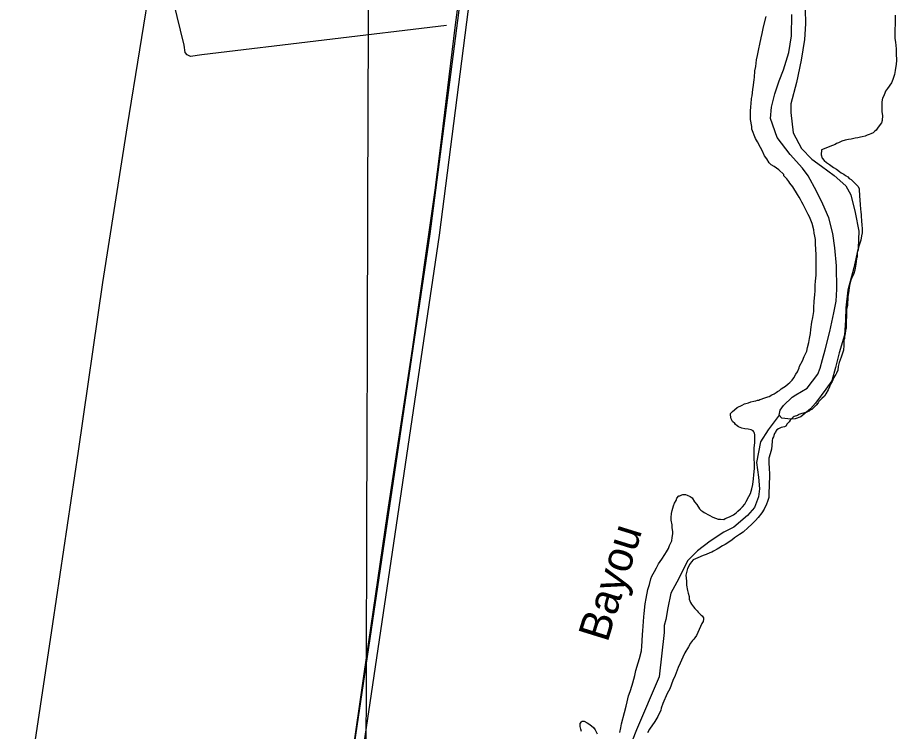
# Model space of a CAD drawing. Extents: x 3161514 to 3199414, y 831166 to 856601.
# Drawn here: x 3169840 to 3172664, y 844859 to 847153 of the extents above; entities that cross this region are included whole.
import ezdxf

# ---------------------------------------------------------------- set-up
doc = ezdxf.new("R2010")
doc.units = 0
for name, color, linetype in [('V-GRID-MAJR', 7, 'Continuous'), ('V-RIVR-IDEN', 7, 'Continuous'), ('V-ROAD-CNTR', 7, 'Continuous'), ('V-SITE-VEGE', 7, 'Continuous'), ('V-TOPO-SHOR', 7, 'Continuous')]:
    doc.layers.add(name, color=color, linetype=linetype)

msp = doc.modelspace()

# ---------------------------------------------------------------- linework, layer by layer
at = {"layer": 'V-GRID-MAJR'}
msp.add_spline([(3170936, 836618.4), (3170954.6, 842678.9), (3170973.1, 848741.2), (3170991.6, 854803.7), (3170991.6, 854805.6)], degree=3, dxfattribs=at)
at = {"layer": 'V-ROAD-CNTR'}
for points in [[(3170729.2, 843056.9), (3170814.5, 843707.1), (3170943.9, 844755.7), (3171195.8, 846454.1), (3171299.1, 847255.9), (3171351.4, 847638.1), (3171399.9, 848031.4), (3171421.5, 848196.3), (3171427.4, 848252.3), (3171427.3, 848291.4), (3171417.9, 848330.6)], [(3170699.4, 843060.8), (3170784.7, 843710.9), (3170914.1, 844759.7), (3171166.1, 846458.2), (3171269.4, 847259.8), (3171321.6, 847642), (3171370.2, 848035.1), (3171391.7, 848199.8), (3171397.4, 848253.8), (3171397.3, 848287.9), (3171388.7, 848323.6)]]:
    msp.add_lwpolyline(points, dxfattribs=at)
at = {"layer": 'V-SITE-VEGE'}
for points in [[(3172367, 846063.4), (3172375.8, 846081.2), (3172378.5, 846092.2), (3172382.1, 846108.3), (3172384.8, 846121.1), (3172387.6, 846137.2), (3172388.6, 846150), (3172392.4, 846173.8), (3172395.2, 846189.1), (3172398, 846208.7), (3172399, 846219.7), (3172399.3, 846241.9), (3172401.3, 846261.5), (3172402.3, 846275.1), (3172402.6, 846293), (3172403.6, 846305.7), (3172405.6, 846325.3), (3172406.5, 846392.6), (3172405, 846406.3), (3172404.4, 846426.7), (3172403.7, 846439.5), (3172401.3, 846450.6), (3172399.7, 846460), (3172398.2, 846470.3), (3172393.3, 846490.8), (3172385.1, 846512.2), (3172380.1, 846519.9), (3172364.4, 846552.5), (3172360.2, 846559.4), (3172356.1, 846568), (3172351.9, 846575.7), (3172346.1, 846584.3), (3172331.1, 846608.4), (3172321.9, 846620.4), (3172317.7, 846625.6), (3172311.8, 846634.2), (3172301.7, 846644.6), (3172301.8, 846648.8), (3172285.8, 846663.5), (3172270.6, 846674), (3172261.3, 846680.1), (3172254.6, 846686.1), (3172247.1, 846699), (3172240.4, 846708.5), (3172233, 846725.6), (3172227.1, 846735.1), (3172217.2, 846753.1), (3172211.4, 846764.3), (3172206.4, 846775.4), (3172203.1, 846784), (3172199.8, 846794.2), (3172199.1, 846802.8), (3172195.2, 846825.8), (3172194.5, 846840.3), (3172194.7, 846851.4), (3172195.7, 846866.7), (3172197.6, 846876.1), (3172198.6, 846892.3), (3172200.5, 846901.6), (3172202.5, 846922), (3172204.3, 846935.6), (3172207.1, 846953.5), (3172208.1, 846960.3), (3172209.2, 846981.6), (3172212, 846995.2), (3172214.8, 847017.3), (3172217.6, 847030.9), (3172221.3, 847052.1), (3172224.9, 847067.4), (3172229.5, 847087.8), (3172232.2, 847101.4), (3172236.8, 847122.7), (3172245.7, 847156.6)], [(3172659.9, 847160.3), (3172658.9, 847085.3), (3172660.4, 847073.4), (3172662.7, 847052), (3172663.3, 847037.5), (3172663.9, 847015.4), (3172662.9, 847003.4), (3172660, 846983), (3172657.3, 846970.3), (3172652.8, 846954.2), (3172647.6, 846943.2), (3172635.4, 846925.4), (3172629.3, 846916.1), (3172627.5, 846912.8), (3172623.1, 846901.7), (3172619.6, 846894.1), (3172616.9, 846882.2), (3172616.8, 846873.7), (3172617.4, 846858.4), (3172617.3, 846849.8), (3172618.8, 846837.9), (3172618.6, 846822.6), (3172616, 846814.9), (3172605.5, 846800.6), (3172598.6, 846791.3), (3172593.4, 846786.3), (3172589.1, 846782.9), (3172581.4, 846779.6), (3172576.2, 846777.1), (3172569.4, 846774.7), (3172563.4, 846772.2), (3172554, 846769.8), (3172548, 846769), (3172539.5, 846766.6), (3172531.8, 846765.8), (3172523.2, 846763.4), (3172518.9, 846761.7), (3172510.4, 846761), (3172499.3, 846758.6), (3172488.2, 846755.3), (3172477.9, 846750.4), (3172471, 846747.9), (3172466.7, 846744.6), (3172458.2, 846741.3), (3172423, 846727.3)], [(3172423, 846727.3), (3172422.6, 846711.6), (3172425.3, 846700.8), (3172432, 846693.8), (3172439.6, 846686.8), (3172449.3, 846680.7), (3172461.7, 846670.6), (3172471.4, 846665.5), (3172481, 846658.4), (3172486.7, 846653.4), (3172494.4, 846649.3), (3172500.2, 846645.3), (3172507.9, 846641.2), (3172511.7, 846636.2), (3172518.5, 846632.1), (3172523.2, 846628.1), (3172533.7, 846617.1), (3172540.4, 846611.1), (3172544.2, 846604.1), (3172544, 846598.3), (3172546.2, 846565), (3172547.8, 846553.2), (3172548.4, 846536.6), (3172549.2, 846529.8), (3172550.9, 846518), (3172550.7, 846511.2), (3172551.5, 846503.3), (3172551.4, 846497.5), (3172553.1, 846487.6), (3172553.7, 846473), (3172553.4, 846461.2), (3172552.2, 846451.5), (3172549, 846437.9), (3172545.8, 846428.2), (3172542.5, 846414.6), (3172541.4, 846406.8), (3172538.2, 846398.1), (3172537.9, 846384.4), (3172535.8, 846378.6), (3172533.4, 846360.1), (3172530, 846341.6), (3172526.8, 846330.9), (3172519.6, 846314.5), (3172516.5, 846305.8), (3172513.2, 846292.2), (3172509.7, 846267.8), (3172507.4, 846255.2), (3172506.8, 846227.8), (3172503.5, 846214.2), (3172502.1, 846154.7), (3172499.9, 846147.9), (3172498.7, 846136.2), (3172497.5, 846129.4), (3172497.4, 846121.5), (3172495.3, 846115.7), (3172494.9, 846099.1), (3172493.5, 846084.5), (3172487.2, 846065.1), (3172486.1, 846061.2), (3172483, 846052.5), (3172479.9, 846044.8), (3172476.6, 846031.2), (3172475.4, 846019.5), (3172471.2, 846009.8), (3172469.2, 846005.9), (3172466.1, 846002.1), (3172463.1, 845996.3), (3172457.9, 845983.7), (3172451.8, 845975.1), (3172448.7, 845966.4), (3172444.5, 845956.7), (3172437.4, 845943.2), (3172433.3, 845936.4), (3172424.3, 845928.8), (3172420.3, 845924.1), (3172414.3, 845919.3), (3172412.2, 845914.5), (3172406.2, 845906.8), (3172392.2, 845893.5), (3172386.3, 845890.7), (3172383.3, 845887.8), (3172380.3, 845886.9), (3172376.4, 845885), (3172371.4, 845884.2), (3172368.5, 845882.3), (3172365.5, 845881.4), (3172359.6, 845880.6), (3172350.6, 845876.9), (3172348.8, 845875.9), (3172345.8, 845874.1), (3172334.9, 845870.4), (3172332, 845868.5), (3172326, 845862.8), (3172323, 845859), (3172319.1, 845853.7), (3172312.7, 845847.7), (3172308.5, 845840.1), (3172304.2, 845837.6), (3172293.1, 845835.2), (3172289.7, 845833.5), (3172285.4, 845831)], [(3171942.9, 845523), (3171940.5, 845537.5), (3171940.6, 845546.1), (3171941.7, 845559.7), (3171943.5, 845569), (3171947.1, 845583.5), (3171950.7, 845592.8), (3171955.9, 845601.2), (3171958.5, 845608), (3171964.6, 845615.6), (3171968, 845616.4), (3171974, 845618.9), (3171977.5, 845620.5), (3171986, 845620.4), (3171991.9, 845618.6), (3172001.2, 845614.3), (3172008, 845609), (3172015.5, 845597), (3172023, 845588.4), (3172031.3, 845573.8), (3172035.6, 845570.3), (3172042.3, 845566), (3172046.5, 845562.5), (3172062.6, 845553.8), (3172074.4, 845547.6), (3172091.4, 845541.4), (3172099.1, 845540.5), (3172109.3, 845540.3), (3172113.6, 845542.8), (3172122.1, 845546.1), (3172129.9, 845549.4), (3172140.2, 845555.2), (3172148.8, 845561.1), (3172154.8, 845567), (3172163.4, 845574.5), (3172169.5, 845580.4), (3172176.4, 845588.8), (3172180.8, 845598.1), (3172189.5, 845613.4), (3172194.8, 845623.5), (3172199.3, 845638.8), (3172202, 845652.4), (3172204.8, 845670.2), (3172205.8, 845683), (3172207.8, 845703.4), (3172208, 845717.1), (3172206.6, 845738.4), (3172206.8, 845754.6), (3172207, 845769.1), (3172209, 845787.8), (3172209.3, 845812.5), (3172207.7, 845816.8), (3172206, 845821.9), (3172203.5, 845825.3), (3172197.6, 845828), (3172187.4, 845830.7), (3172177.2, 845831.7), (3172167, 845833.5), (3172156.8, 845837.9), (3172151.8, 845840.5), (3172146.7, 845844.9), (3172144.2, 845848.3), (3172137.5, 845855.2), (3172132.5, 845863), (3172130.9, 845874.9), (3172131, 845880), (3172137.1, 845886.8), (3172143.1, 845892.6), (3172152.6, 845900.2), (3172168, 845907.6), (3172175.7, 845911.8), (3172188.6, 845915), (3172196.3, 845917.5), (3172205.7, 845919.9), (3172211.7, 845920.7), (3172217.7, 845923.1), (3172221.9, 845923.9), (3172225.4, 845925.6), (3172228.8, 845926.4), (3172238.2, 845929.7), (3172244.2, 845932.2), (3172251, 845934.6), (3172254.5, 845935.4), (3172263.9, 845940.4), (3172271.6, 845943.7), (3172277.6, 845947.9), (3172282, 845951.2), (3172288, 845954.6), (3172294, 845959.6), (3172301.7, 845965.4), (3172307.8, 845968.8), (3172316.4, 845975.5), (3172321.5, 845979.7), (3172328.5, 845988.1), (3172334.5, 845994.8), (3172340.7, 846006.7), (3172345.9, 846014.3), (3172351.2, 846027), (3172352.9, 846032.1), (3172361.7, 846049.8), (3172367, 846063.4)], [(3172285.4, 845831), (3172279.4, 845827.7), (3172275.9, 845823.5), (3172275, 845821), (3172272.4, 845816.7), (3172270.7, 845813.3), (3172268.9, 845805.7), (3172266.2, 845800.6), (3172264.4, 845793.8), (3172264.4, 845790.4), (3172262.4, 845765.7), (3172257.9, 845751.3), (3172254.3, 845736.9), (3172254, 845716.4), (3172254.8, 845709.6), (3172254.7, 845701.9), (3172256.2, 845688.3), (3172255.5, 845642.3), (3172253.7, 845631.2), (3172253.4, 845610.8), (3172249.8, 845597.2), (3172246.3, 845589.6), (3172238.4, 845573.5), (3172231.4, 845561.7), (3172220.1, 845546.5), (3172211.5, 845536.4), (3172198.5, 845523.8), (3172187.3, 845513.7), (3172171.8, 845499.4), (3172159.7, 845491.9), (3172143.4, 845481.1), (3172134.8, 845473.5), (3172114.1, 845459.3), (3172105.5, 845455.2), (3172093.5, 845447.7), (3172087.5, 845444.3), (3172076.3, 845438.5), (3172070.3, 845435.2), (3172064.3, 845432.7), (3172052.3, 845426.9), (3172042.9, 845424.5), (3172025.8, 845417.1), (3172011.2, 845410.5), (3172005.1, 845403.7), (3171999.1, 845395.3), (3171996.4, 845389.4), (3171992.9, 845382.6), (3171989.3, 845369.9), (3171987.5, 845360.5), (3171988.9, 845341.7), (3171989.6, 845329), (3171992.8, 845311.9), (3171995.2, 845303.3), (3171997.6, 845292.2), (3171998.4, 845283.7), (3172002.5, 845273.4), (3172005.8, 845268.2), (3172011.7, 845258.8), (3172015.9, 845253.6), (3172020.1, 845250.1), (3172023.4, 845246.7), (3172026.8, 845242.4), (3172030.1, 845238.9), (3172036.9, 845232.9), (3172040.2, 845230.3), (3172043.6, 845224.3), (3172043.5, 845220), (3172042.5, 845212.3), (3172038.2, 845205.6), (3172021.5, 845166.6), (3172016.3, 845159.9), (3172012.8, 845154.8), (3172008.5, 845151.5), (3172002.4, 845143), (3171996.3, 845131.2), (3171984.1, 845110.9), (3171977.9, 845097.3), (3171969.1, 845078.7), (3171963, 845064.3), (3171953.2, 845038.9), (3171945.3, 845022), (3171935.6, 844995.7), (3171927.7, 844980.4), (3171913.6, 844948.3), (3171908.3, 844933.8), (3171906.5, 844927.1), (3171896.9, 844906.7), (3171887.3, 844890.7), (3171870.8, 844866.2), (3171863.8, 844854.4)], [(3171775.2, 844855.6), (3171777.9, 844870.9), (3171780.7, 844882.8), (3171789.7, 844919.3), (3171795.1, 844940.5), (3171798.7, 844954.1), (3171803.2, 844972.8), (3171808.5, 844987.2), (3171814.8, 845007.6), (3171816.6, 845015.2), (3171822.9, 845038.1), (3171826.5, 845055.1), (3171833.6, 845078.9), (3171838.1, 845093.3), (3171844.4, 845117.9), (3171845.5, 845132.4), (3171847.4, 845149.4), (3171847.7, 845171.6), (3171848.7, 845180.9), (3171849.8, 845198), (3171851.7, 845210.7), (3171852.7, 845227.7), (3171852.9, 845237.1), (3171854.7, 845248.2), (3171856.7, 845268.6), (3171859.5, 845285.6), (3171865, 845314.5), (3171870.4, 845331.5), (3171874.9, 845349.3), (3171878.4, 845357.8), (3171887.1, 845373), (3171893.3, 845384.8), (3171899.4, 845397.5), (3171909.8, 845412.7), (3171919.4, 845427.1), (3171925.5, 845436.4), (3171931.6, 845446.5), (3171935.1, 845456.7), (3171942.2, 845471.1), (3171943.2, 845482.1), (3171945.9, 845494), (3171946, 845501.7), (3171943.6, 845513.6), (3171942.9, 845523)], [(3171652.5, 844858.1), (3171650.1, 844865.8), (3171647.6, 844874.4), (3171647.8, 844883.8), (3171652.1, 844889.7), (3171653, 844892.2), (3171660.6, 844892.1), (3171669.9, 844886.9), (3171678.4, 844880.8), (3171690.2, 844871.2), (3171696, 844863.5), (3171702.7, 844851.5)]]:
    msp.add_lwpolyline(points, dxfattribs=at)
at = {"layer": 'V-TOPO-SHOR'}
for points in [[(3171209, 848216.8), (3171349.6, 848264.2), (3171395.4, 848281.6), (3171376.4, 848130), (3171318, 847678.4), (3171245.4, 847121), (3171196.4, 846724.7), (3171180.6, 846598.4), (3171108, 846086.8), (3171027.5, 845557.9), (3170951.7, 845036.8), (3170874.3, 844498.4), (3170842.7, 844321.5)], [(3171218.5, 847127.3), (3170432.2, 847032.6), (3170395.9, 847027.9), (3170384.8, 847032.6), (3170378.5, 847040.5), (3170375.4, 847064.2), (3170294.8, 847394.2), (3170200.1, 847781), (3170181.1, 847842.6)], [(3170271.1, 847294.7), (3170192.2, 846805.2), (3170113.2, 846301.5), (3170034.3, 845760), (3169952.2, 845204.2), (3169873.2, 844675.2), (3169840.1, 844466.8)], [(3172370.9, 847179.7), (3172371.5, 847132.5), (3172368.6, 847082), (3172357.6, 847016.3), (3172343, 846943.8), (3172325, 846875.6), (3172324.4, 846847.4), (3172332.2, 846782.9), (3172359.3, 846732.5), (3172391.9, 846697.4), (3172423.1, 846675.2), (3172464.3, 846645.1), (3172501.3, 846611.7), (3172517.7, 846583), (3172531.8, 846526.9), (3172543.2, 846466.6), (3172541, 846411.8), (3172526.6, 846348.7), (3172507.8, 846277.2), (3172501.3, 846219.9), (3172500.3, 846180.5), (3172496.6, 846132.6), (3172479.8, 846075.6), (3172468.4, 846028.7), (3172456.2, 845985.3), (3172436.7, 845958.3), (3172403.9, 845913.7), (3172388, 845895.2), (3172356.5, 845869.4), (3172338.4, 845863.8), (3172324.6, 845862.4), (3172295.6, 845865.7), (3172287.2, 845875.3), (3172290.2, 845890.7), (3172300.8, 845906.7), (3172328.9, 845932.6), (3172341.1, 845940.9), (3172377.5, 845962)], [(3172377.5, 845962), (3172411.1, 846006.6), (3172418.5, 846026.1), (3172426, 846054.3), (3172435.3, 846084.9), (3172450.4, 846143.7), (3172463, 846204.2), (3172469.9, 846241.8), (3172472.6, 846280.3), (3172470.9, 846354.9), (3172466.3, 846412.4), (3172459.7, 846458.9), (3172446.4, 846509.8), (3172426.9, 846553.1), (3172407.3, 846594.7), (3172380.2, 846644.2), (3172361.9, 846668.7), (3172322.7, 846712.5), (3172281.2, 846767.5), (3172259.5, 846828), (3172262.1, 846864.8), (3172273.4, 846908.3), (3172287.2, 846949.1), (3172301, 846984.7), (3172318.6, 847040.9), (3172326.7, 847093.8), (3172327.5, 847162.4)], [(3172287.2, 845875.3), (3172252, 845827.5), (3172226.7, 845789.6), (3172214.1, 845723.3), (3172220.4, 845675.9), (3172223.5, 845638), (3172220.4, 845612.7), (3172207.7, 845578), (3172185.6, 845552.7), (3172141.4, 845514.8), (3172109.8, 845499), (3172065.6, 845470.6), (3172024.6, 845439), (3171993, 845407.5), (3171977.2, 845375.9), (3171958.3, 845338), (3171939.3, 845303.3), (3171929.8, 845255.9), (3171923.5, 845218), (3171917.2, 845199), (3171917.2, 845176.9), (3171901.4, 845034.8), (3171828.8, 844864.3), (3171759.3, 844687.5)]]:
    msp.add_lwpolyline(points, dxfattribs=at)

# ---------------------------------------------------------------- texts
at = {"layer": 'V-RIVR-IDEN'}
msp.add_text('Bayou', height=100, rotation=72.7839, dxfattribs=at).set_placement((3171735.4, 845142.4))

doc.saveas('drawing.dxf')
